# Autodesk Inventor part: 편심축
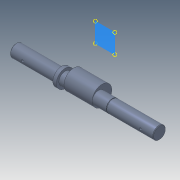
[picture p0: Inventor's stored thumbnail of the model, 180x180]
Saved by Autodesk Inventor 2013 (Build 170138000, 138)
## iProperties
Manager: 한국ATC센터
Company: 한국ATC센터
Created: 2014-10
Part Number: 편심축
Document SubType Name: Modeling
Designer: 한국ATC센터
Density: 7.86 g/cm^3
Material: 강, 연강
Mass: 1420.77 g
Surface Area: 286.546 cm^2
Volume: 180.76 cm^3
Author: KYOUNG IL JANG
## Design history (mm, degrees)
sketch "스케치1"
  geometry: L1 (-142, 0)-(142, 0); L2 (-142, 0)-(-142, 12.5); L3 (-142, 12.5)-(-52, 12.5); L4 (-52, 12.5)-(-52, 17.5); L5 (-52, 17.5)-(-45, 17.5); L6 (-45, 17.5)-(-45, 12.5); L7 (-45, 12.5)-(48.65, 12.5); L8 (48.65, 12.5)-(48.65, 11.95); L9 (48.65, 11.95)-(50, 11.95); L10 (50, 11.95)-(50, 12.5); L11 (50, 12.5)-(142, 12.5); L12 (142, 12.5)-(142, 0); L13 (109, 12.5)-(109, 9.1); L14 (109, 9.1)-(134, 9.1); L15 (134, 9.1)-(134, 12.5); L16 (117, -12.5)-(119.5, -12.5); L17 (119.5, -12.5)-(117, -10); L18 (117, -10)-(117, -12.5); L19 (-109, 12.5)-(-109, 9.1); L20 (-109, 9.1)-(-134, 9.1); L21 (-134, 9.1)-(-134, 12.5); L22 (-117, -12.5)-(-117, -10); L23 (-117, -10)-(-114.5, -12.5); L24 (-114.5, -12.5)-(-117, -12.5); 2 further points
  constraints: 48 end point, 11 parallel, 8 perpendicular, 5 collinear, 4 point on line, 1 coincident, 1 horizontal, 1 midpoint, 1 vertical
  dimensions: "d0" = 284 distance of L1.start L1.end (derived); "d1" = 25 diameter of L3 L1; "d2" = 35 diameter of L5 L1; "d3" = 90 distance of L2.end L3.end; "d4" = 187 distance between parallel lines of L12 L6; "d6" = 1.35 distance of L8.end L9.end; "d7" = 23.9 diameter of L9 L1; "d8" = 3.4 distance between parallel lines of L14 L11; "d9" = 8 distance between parallel lines of L15 L12; "d10" = 25 distance of L13.end L14.end; "d11" = 25 diameter of L16 L1 (= d1); "d12" = 25 distance from line of L12 L16.start; "d13" = 45 deg angle of L17 L18; "d14" = 5 diameter of L16.end L18; "d27" = 92 distance between parallel lines of L10 L12; "d32" = 7 distance of L4.end L5.end; "d33" = 8 distance between parallel lines of L2 L21; "d34" = 25 distance between parallel lines of L21 L19; "d35" = 3.4 distance between parallel lines of L3 L20; "d36" = 25 distance from line of L22.start L2; "d37" = 5 diameter of L23.end L22
revolve "회전1" stored, may be unused: angle "d15" = 90 deg
revolve "회전2" stored, may be unused: angle "d16" = 90 deg
revolve "회전3" stored, may be unused: angle "d38" = 90 deg
extrude "돌출1" cut sketch "스케치1" stored distance "d17" = 8; taper "d18" = 0 deg
fillet "모깎기1" dims "d19" = 4
node "작업 평면1"
sketch "스케치2"
  geometry: C1 r 12.5 at (0, 0) reference; C2 r 19.5 at (0, 7); 1 further point
  constraints: 1 centre point, 1 tangent, 1 vertical alignment
  dimensions: "d21" = 7 distance of point (0, 0) C2.centre; "d30" = 39 diameter of C2 (derived)
extrude "돌출2" join sketch "스케치2" distance "d22" = 56; taper "d23" = 0 deg
chamfer "모따기1" distance "d24" = 1; stored, may be unused: second distance "d25" = 2, angle "d26" = 45 deg
node "솔리드1"
other parameters: "d20" = 16
